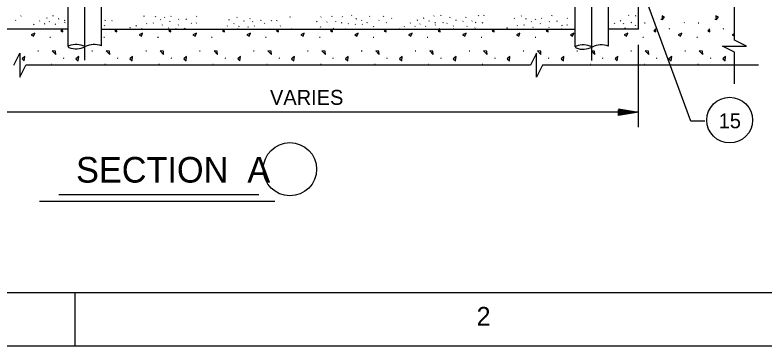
# Model space of a CAD drawing. Extents: x -0.2 to 13.5, y -0.2 to 9.5.
# Drawn here: x 7.896 to 10.235, y 0 to 1.035 of the extents above; entities that cross this region are included whole.
import ezdxf

# ---------------------------------------------------------------- set-up
doc = ezdxf.new("R2010")
doc.units = 0
for name, color, linetype in [('Level 0', 7, 'Continuous'), ('Level 1', 7, 'Continuous'), ('Level 13', 7, 'Continuous'), ('Level 2', 7, 'Continuous'), ('Level 3', 7, 'Continuous'), ('Level 50', 7, 'Continuous')]:
    doc.layers.add(name, color=color, linetype=linetype)

msp = doc.modelspace()

# ---------------------------------------------------------------- linework, layer by layer
at = {"layer": 'Level 0'}
for p, q in [((7.9157, 1.0321), (7.9145, 1.0308)), ((8.0152, 1.0323), (8.0134, 1.031)), ((8.2993, 1.0318), (8.2981, 1.0303)), ((8.3348, 1.03), (8.3336, 1.0286)), ((8.384, 1.0318), (8.3829, 1.0303)), ((8.4645, 1.0317), (8.4633, 1.0303)), ((8.7552, 1.0293), (8.7546, 1.0272)), ((8.8525, 1.0296), (8.8513, 1.0282)), ((8.8857, 1.0309), (8.8846, 1.0295)), ((8.9191, 1.0305), (8.9178, 1.0291)), ((8.9485, 1.0348), (8.9473, 1.0334)), ((9.0047, 1.0314), (9.0035, 1.03)), ((9.0475, 1.031), (9.0463, 1.0295)), ((9.2052, 1.0325), (9.204, 1.0311)), ((9.2259, 1.0342), (9.2247, 1.0328)), ((9.344, 1.0329), (9.3428, 1.0315)), ((9.36, 1.0342), (9.3588, 1.0328)), ((9.4778, 1.0323), (9.4766, 1.0309)), ((9.573, 1.0332), (9.5718, 1.0318)), ((9.8132, 1.0343), (9.812, 1.0329)), ((9.8348, 1.0321), (9.833, 1.0315)), ((7.8988, 1.0188), (7.8976, 1.0173)), ((7.9557, 1.006), (7.9545, 1.0046)), ((7.9739, 1.0172), (7.9727, 1.0158)), ((7.989, 1.0073), (7.9878, 1.0059)), ((7.9955, 1.0259), (7.9943, 1.0244)), ((8.0041, 1.0146), (8.0029, 1.0132)), ((8.0223, 1.0068), (8.0211, 1.0054)), ((8.0327, 1.0233), (8.0315, 1.0219)), ((8.052, 1.0174), (8.0499, 1.0169)), ((8.0517, 1.0112), (8.0505, 1.0098)), ((8.1775, 1.0185), (8.1764, 1.0171)), ((8.1997, 1.0178), (8.1982, 1.0163)), ((8.3084, 1.0088), (8.3072, 1.0074)), ((8.3292, 1.0106), (8.3279, 1.0092)), ((8.3521, 1.0214), (8.3509, 1.0199)), ((8.3642, 1.0283), (8.363, 1.0269)), ((8.3797, 1.0153), (8.3786, 1.0139)), ((8.4078, 1.0218), (8.4066, 1.0204)), ((8.4318, 1.0227), (8.4302, 1.0211)), ((8.4472, 1.0092), (8.446, 1.0079)), ((8.4632, 1.0106), (8.462, 1.0092)), ((8.5646, 1.0199), (8.5635, 1.0185)), ((8.5811, 1.0086), (8.5799, 1.0072)), ((8.5902, 1.0281), (8.589, 1.0267)), ((8.6112, 1.0163), (8.6101, 1.0143)), ((8.6304, 1.0242), (8.6292, 1.0228)), ((8.639, 1.0147), (8.6378, 1.0133)), ((8.6637, 1.0186), (8.6625, 1.0171)), ((8.6762, 1.0095), (8.675, 1.0081)), ((8.697, 1.0173), (8.6958, 1.0159)), ((8.7143, 1.0173), (8.7131, 1.0159)), ((8.8396, 1.0155), (8.838, 1.0139)), ((8.8711, 1.0137), (8.8699, 1.0123)), ((8.8976, 1.0149), (8.8969, 1.0133)), ((8.9165, 1.0106), (8.9153, 1.0092)), ((8.938, 1.0084), (8.9362, 1.0078)), ((8.9601, 1.0067), (8.9589, 1.0053)), ((8.9623, 1.0236), (8.9611, 1.0222)), ((8.9796, 1.0193), (8.9784, 1.0178)), ((8.9813, 1.0059), (8.98, 1.0049)), ((8.9965, 1.0111), (8.9953, 1.0097)), ((9.0337, 1.0188), (9.0325, 1.0174)), ((9.0561, 1.0119), (9.055, 1.0105)), ((9.0731, 1.0253), (9.0719, 1.0239)), ((9.1312, 1.0104), (9.13, 1.009)), ((9.1528, 1.0191), (9.1516, 1.0176)), ((9.1615, 1.0078), (9.1603, 1.0064)), ((9.1725, 1.0255), (9.1707, 1.0242)), ((9.19, 1.0165), (9.1888, 1.015)), ((9.2094, 1.0106), (9.2072, 1.0101)), ((9.2333, 1.0113), (9.2321, 1.0099)), ((9.2462, 1.0096), (9.2451, 1.0082)), ((9.2541, 1.0277), (9.2528, 1.0263)), ((9.2735, 1.0186), (9.2723, 1.0173)), ((9.2959, 1.0156), (9.2945, 1.0146)), ((9.3042, 1.0278), (9.303, 1.0263)), ((9.3236, 1.0169), (9.3225, 1.0155)), ((9.3349, 1.0117), (9.3337, 1.0103)), ((9.357, 1.011), (9.3556, 1.0095)), ((9.4566, 1.0249), (9.4555, 1.0235)), ((9.4921, 1.0232), (9.4909, 1.0218)), ((9.5094, 1.0145), (9.5082, 1.0131)), ((9.5215, 1.0215), (9.5203, 1.0201)), ((9.5371, 1.0085), (9.5359, 1.0071)), ((9.5414, 1.0249), (9.5402, 1.0235)), ((9.5652, 1.015), (9.564, 1.0136)), ((9.5891, 1.0159), (9.5875, 1.0143)), ((9.6218, 1.0249), (9.6206, 1.0235)), ((9.7685, 1.0095), (9.7674, 1.0075)), ((9.7877, 1.0174), (9.7865, 1.016)), ((9.7963, 1.0079), (9.7952, 1.0064)), ((9.821, 1.0118), (9.8198, 1.0103)), ((9.8638, 1.0094), (9.8616, 1.0094)), ((9.9151, 1.0206), (9.9134, 1.0207)), ((9.9873, 1.0108), (9.9856, 1.0111)), ((10.0321, 1.0094), (10.0299, 1.0094)), ((10.0834, 1.0206), (10.0818, 1.0207)), ((7.9429, 0.9918), (7.942, 0.9909)), ((8.0008, 0.9912), (8.0007, 0.9909)), ((8.1763, 1.0017), (8.1751, 1.0003)), ((8.2562, 0.9909), (8.2548, 0.9902)), ((8.2561, 0.9954), (8.2549, 0.994)), ((8.2757, 1.0018), (8.274, 1.0005)), ((8.2932, 0.9928), (8.2921, 0.9914)), ((8.3573, 1.0041), (8.3561, 1.0027)), ((8.3767, 0.995), (8.3755, 0.9936)), ((8.3991, 0.992), (8.3977, 0.991)), ((8.4074, 1.0041), (8.4062, 1.0027)), ((8.4245, 0.9909), (8.4231, 0.9902)), ((8.4269, 0.9933), (8.4257, 0.9919)), ((8.5599, 1.0013), (8.5587, 0.9999)), ((8.5929, 0.9909), (8.5915, 0.9902)), ((8.5953, 0.9996), (8.5941, 0.9981)), ((8.6247, 0.9978), (8.6235, 0.9964)), ((8.6446, 1.0013), (8.6434, 0.9999)), ((8.6684, 0.9913), (8.668, 0.9909)), ((8.6923, 0.9922), (8.691, 0.9909)), ((8.7251, 1.0013), (8.7239, 0.9999)), ((8.7612, 0.9909), (8.7598, 0.9902)), ((8.8507, 0.9976), (8.8495, 0.9963)), ((8.8909, 0.9938), (8.8898, 0.9924)), ((8.9295, 0.9909), (8.9281, 0.9902)), ((9.0158, 0.9988), (9.0151, 0.9968)), ((9.0979, 0.9909), (9.0965, 0.9902)), ((9.1131, 0.9992), (9.1118, 0.9978)), ((9.1463, 1.0005), (9.1451, 0.9991)), ((9.1796, 1), (9.1784, 0.9986)), ((9.209, 1.0044), (9.2079, 1.003)), ((9.2229, 0.9931), (9.2217, 0.9917)), ((9.2653, 1.0009), (9.2641, 0.9996)), ((9.2662, 0.9909), (9.2648, 0.9902)), ((9.3081, 1.0005), (9.3069, 0.9991)), ((9.3336, 0.9949), (9.3324, 0.9935)), ((9.4331, 0.995), (9.4313, 0.9937)), ((9.4345, 0.9909), (9.4331, 0.9902)), ((9.4657, 1.002), (9.4645, 1.0006)), ((9.4865, 1.0038), (9.4852, 1.0023)), ((9.5146, 0.9973), (9.5134, 0.9959)), ((9.5647, 0.9973), (9.5636, 0.9959)), ((9.6029, 0.9909), (9.6015, 0.9902)), ((9.6045, 1.0024), (9.6033, 1.0011)), ((9.6205, 1.0038), (9.6194, 1.0023)), ((9.7712, 0.9909), (9.7698, 0.9902)), ((9.7821, 0.991), (9.7819, 0.9909)), ((9.8019, 0.9945), (9.8008, 0.9931)), ((9.8336, 1.0027), (9.8324, 1.0013)), ((9.9401, 0.9912), (9.9381, 0.9902)), ((10.1085, 0.9912), (10.1065, 0.9902)), ((8.0073, 0.9643), (8.0052, 0.9643)), ((8.1756, 0.9643), (8.1735, 0.9643)), ((8.344, 0.9643), (8.3418, 0.9643)), ((8.5123, 0.9643), (8.5102, 0.9643)), ((8.6806, 0.9643), (8.6785, 0.9643)), ((8.849, 0.9643), (8.8468, 0.9643)), ((9.0173, 0.9643), (9.0152, 0.9643)), ((9.1856, 0.9643), (9.1835, 0.9643)), ((9.354, 0.9643), (9.3518, 0.9643)), ((9.5223, 0.9643), (9.5202, 0.9643)), ((9.859, 0.9643), (9.8568, 0.9643)), ((10.0273, 0.9643), (10.0252, 0.9643)), ((7.97, 0.9219), (7.9677, 0.9219)), ((8.1383, 0.9219), (8.1361, 0.9219)), ((8.3066, 0.9219), (8.3044, 0.9219)), ((8.475, 0.9219), (8.4727, 0.9219)), ((8.6433, 0.9219), (8.6411, 0.9219)), ((8.8116, 0.9219), (8.8094, 0.9219)), ((8.98, 0.9219), (8.9777, 0.9219)), ((9.1483, 0.9219), (9.1461, 0.9219)), ((9.3166, 0.9219), (9.3144, 0.9219)), ((9.485, 0.9219), (9.4827, 0.9219)), ((9.6533, 0.9219), (9.6511, 0.9219)), ((9.8216, 0.9219), (9.8194, 0.9219)), ((9.99, 0.9219), (9.9877, 0.9219)), ((8.0497, 0.8994), (8.0476, 0.8997)), ((8.2181, 0.8994), (8.2159, 0.8997)), ((8.3864, 0.8994), (8.3842, 0.8997)), ((8.5547, 0.8994), (8.5526, 0.8997)), ((8.7231, 0.8994), (8.7209, 0.8997)), ((8.8914, 0.8994), (8.8892, 0.8997)), ((9.0597, 0.8994), (9.0576, 0.8997)), ((9.2281, 0.8994), (9.2259, 0.8997)), ((9.3964, 0.8994), (9.3942, 0.8997)), ((9.5647, 0.8994), (9.5626, 0.8997)), ((9.7331, 0.8994), (9.7309, 0.8997)), ((9.9014, 0.8994), (9.8992, 0.8997)), ((10.0697, 0.8994), (10.0676, 0.8997)), ((7.9718, 0.8782), (7.9706, 0.8779)), ((8.0106, 0.8805), (8.009, 0.8799)), ((8.1401, 0.8782), (8.139, 0.8779)), ((8.1789, 0.8805), (8.1773, 0.8799)), ((8.3084, 0.8782), (8.3073, 0.8779)), ((8.3473, 0.8805), (8.3456, 0.8799)), ((8.4768, 0.8782), (8.4756, 0.8779)), ((8.5156, 0.8805), (8.514, 0.8799)), ((8.6451, 0.8782), (8.644, 0.8779)), ((8.6839, 0.8805), (8.6823, 0.8799)), ((8.8134, 0.8782), (8.8123, 0.8779)), ((8.8523, 0.8805), (8.8506, 0.8799)), ((8.9818, 0.8782), (8.9806, 0.8779)), ((9.0206, 0.8805), (9.019, 0.8799)), ((9.1501, 0.8782), (9.149, 0.8779)), ((9.1889, 0.8805), (9.1873, 0.8799)), ((9.3184, 0.8782), (9.3173, 0.8779)), ((9.3573, 0.8805), (9.3556, 0.8799)), ((9.4868, 0.8782), (9.4856, 0.8779)), ((9.5256, 0.8805), (9.524, 0.8799)), ((9.6551, 0.8782), (9.654, 0.8779)), ((9.6939, 0.8805), (9.6923, 0.8799)), ((9.8234, 0.8782), (9.8223, 0.8779)), ((9.8623, 0.8805), (9.8606, 0.8799)), ((9.9918, 0.8782), (9.9906, 0.8779)), ((10.0306, 0.8805), (10.029, 0.8799))]:
    msp.add_line(p, q, dxfattribs=at)
for points in [[(9.9175, 1.02), (9.9246, 1.028), (9.9167, 1.0322)], [(10.0858, 1.02), (10.093, 1.028), (10.085, 1.0322)], [(9.8975, 0.9827), (9.8963, 0.9919), (9.8912, 0.9842)], [(10.0658, 0.9827), (10.0646, 0.9919), (10.0595, 0.9842)], [(7.9542, 0.9684), (7.9582, 0.9786), (7.9471, 0.9732)], [(8.2909, 0.9684), (8.2948, 0.9786), (8.2838, 0.9732)], [(8.4592, 0.9684), (8.4632, 0.9786), (8.4521, 0.9732)], [(8.6276, 0.9684), (8.6315, 0.9786), (8.6205, 0.9732)], [(8.7959, 0.9684), (8.7998, 0.9786), (8.7888, 0.9732)], [(8.9642, 0.9684), (8.9682, 0.9786), (8.9571, 0.9732)], [(9.1326, 0.9684), (9.1365, 0.9786), (9.1255, 0.9732)], [(9.3009, 0.9684), (9.3048, 0.9786), (9.2938, 0.9732)], [(9.4692, 0.9684), (9.4732, 0.9786), (9.4621, 0.9732)], [(9.6376, 0.9684), (9.6415, 0.9786), (9.6305, 0.9732)], [(9.8059, 0.9684), (9.8098, 0.9786), (9.7988, 0.9732)], [(9.9742, 0.9684), (9.9782, 0.9786), (9.9671, 0.9732)], [(8.0229, 0.9221), (8.0129, 0.9227), (8.0238, 0.9116)], [(8.1913, 0.9221), (8.1813, 0.9227), (8.1921, 0.9116)], [(8.3596, 0.9221), (8.3496, 0.9227), (8.3604, 0.9116)], [(8.5279, 0.9221), (8.5179, 0.9227), (8.5288, 0.9116)], [(8.6963, 0.9221), (8.6863, 0.9227), (8.6971, 0.9116)], [(8.8646, 0.9221), (8.8546, 0.9227), (8.8654, 0.9116)], [(9.0329, 0.9221), (9.0229, 0.9227), (9.0338, 0.9116)], [(9.2013, 0.9221), (9.1913, 0.9227), (9.2021, 0.9116)], [(9.3696, 0.9221), (9.3596, 0.9227), (9.3704, 0.9116)], [(9.5379, 0.9221), (9.5279, 0.9227), (9.5388, 0.9116)], [(9.7063, 0.9221), (9.6963, 0.9227), (9.7071, 0.9116)], [(9.8746, 0.9221), (9.8646, 0.9227), (9.8754, 0.9116)], [(10.0429, 0.9221), (10.0329, 0.9227), (10.0438, 0.9116)], [(7.9269, 0.9054), (7.9183, 0.8979), (7.9254, 0.8919)], [(8.0952, 0.9054), (8.0867, 0.8979), (8.0938, 0.8919)], [(8.2636, 0.9054), (8.255, 0.8979), (8.2621, 0.8919)], [(8.4319, 0.9054), (8.4233, 0.8979), (8.4304, 0.8919)], [(8.6002, 0.9054), (8.5917, 0.8979), (8.5988, 0.8919)], [(8.7686, 0.9054), (8.76, 0.8979), (8.7671, 0.8919)], [(8.9369, 0.9054), (8.9283, 0.8979), (8.9354, 0.8919)], [(9.1052, 0.9054), (9.0967, 0.8979), (9.1038, 0.8919)], [(9.2736, 0.9054), (9.265, 0.8979), (9.2721, 0.8919)], [(9.4419, 0.9054), (9.4333, 0.8979), (9.4404, 0.8919)], [(9.6102, 0.9054), (9.6017, 0.8979), (9.6088, 0.8919)], [(9.7786, 0.9054), (9.77, 0.8979), (9.7771, 0.8919)], [(9.9469, 0.9054), (9.9383, 0.8979), (9.9454, 0.8919)], [(10.1152, 0.9054), (10.1067, 0.8979), (10.1138, 0.8919)]]:
    msp.add_lwpolyline(points, close=True, dxfattribs=at)
for points in [[(8.044, 0.9909), (8.0395, 0.9842), (8.0458, 0.9827)], [(8.0458, 0.9827), (8.0448, 0.9909)], [(8.2123, 0.9909), (8.2078, 0.9842), (8.2141, 0.9827)], [(8.2141, 0.9827), (8.2131, 0.9909)], [(8.3806, 0.9909), (8.3762, 0.9842), (8.3825, 0.9827)], [(8.3825, 0.9827), (8.3814, 0.9909)], [(8.549, 0.9909), (8.5445, 0.9842), (8.5508, 0.9827)], [(8.5508, 0.9827), (8.5498, 0.9909)], [(8.7173, 0.9909), (8.7128, 0.9842), (8.7191, 0.9827)], [(8.7191, 0.9827), (8.7181, 0.9909)], [(8.8856, 0.9909), (8.8812, 0.9842), (8.8875, 0.9827)], [(8.8875, 0.9827), (8.8864, 0.9909)], [(9.054, 0.9909), (9.0495, 0.9842), (9.0558, 0.9827)], [(9.0558, 0.9827), (9.0548, 0.9909)], [(9.2223, 0.9909), (9.2178, 0.9842), (9.2241, 0.9827)], [(9.2241, 0.9827), (9.2231, 0.9909)], [(9.3906, 0.9909), (9.3862, 0.9842), (9.3925, 0.9827)], [(9.3925, 0.9827), (9.3914, 0.9909)], [(9.559, 0.9909), (9.5545, 0.9842), (9.5608, 0.9827)], [(9.5608, 0.9827), (9.5598, 0.9909)], [(10.1435, 0.9772), (10.1355, 0.9732), (10.1426, 0.9684)], [(10.1426, 0.9684), (10.1435, 0.971)]]:
    msp.add_lwpolyline(points, dxfattribs=at)
at = {"layer": 'Level 1'}
msp.add_line((8.0833, 0.1667), (8.0833, 0), dxfattribs=at)
for points in [[(0, 9.3333), (13.3333, 9.3333), (13.3333, 0), (0, 0)], [(0.5, 9.1667), (13.1667, 9.1667), (13.1667, 0.1667), (0.5, 0.1667)]]:
    msp.add_lwpolyline(points, close=True, dxfattribs=at)
at = {"layer": 'Level 13'}
for p, q in [((8.0619, 0.9365), (8.0619, 1.1144)), ((8.1661, 0.9389), (8.1661, 1.1144)), ((9.6452, 0.9354), (9.6452, 1.1132)), ((9.7494, 0.9377), (9.7494, 1.1132))]:
    msp.add_line(p, q, dxfattribs=at)
for points in [[(10.1435, 0.919), (10.106, 0.9376), (10.181, 0.9376), (10.1435, 0.9563)], [(7.8929, 0.8779), (7.9115, 0.9154), (7.9115, 0.8405), (7.9303, 0.8779)], [(9.543, 0.8779), (9.5244, 0.8404), (9.5244, 0.9153), (9.5057, 0.8779)]]:
    msp.add_lwpolyline(points, dxfattribs=at)
for centre, radius, start, end in [((8.0659, 0.9359), 0.00313, 110.1936, 249.8064), ((8.0869, 0.879), 0.0638, 63.3929, 110.1936), ((8.0869, 0.9929), 0.0638, 249.8064, 296.6071), ((8.144, 0.879), 0.0638, 69.8081, 116.6071), ((9.6493, 0.9348), 0.00313, 110.1936, 249.8064), ((9.6702, 0.8778), 0.0638, 63.3929, 110.1936), ((9.7274, 0.8778), 0.0638, 69.8081, 116.6071), ((9.6702, 0.9917), 0.0638, 249.8064, 296.6071)]:
    msp.add_arc(centre, radius, start, end, dxfattribs=at)
at = {"layer": 'Level 2'}
for p, q in [((8.114, 0.8941), (8.114, 1.4695)), ((9.6973, 0.893), (9.6973, 1.4684)), ((9.8431, 0.9909), (9.8431, 1.3242)), ((10.1435, 0.9563), (10.1435, 1.2171)), ((8.0619, 0.9909), (7.8119, 0.9909)), ((8.1661, 0.9909), (9.6452, 0.9909)), ((9.8431, 0.9909), (9.7494, 0.9909)), ((9.8431, 0.6846), (9.8431, 0.9419)), ((10.1435, 0.82), (10.1435, 0.919)), ((9.5057, 0.8779), (7.9303, 0.8779)), ((10.218, 0.8779), (9.543, 0.8779)), ((9.8431, 0.7308), (7.8119, 0.7308))]:
    msp.add_line(p, q, dxfattribs=at)
msp.add_circle((10.1281, 0.7063), 0.0714, dxfattribs=at)
at = {"layer": 'Level 3'}
for p, q in [((8.0335, 0.4739), (8.6582, 0.4739)), ((7.9731, 0.453), (8.7079, 0.453))]:
    msp.add_line(p, q, dxfattribs=at)
msp.add_lwpolyline([(10.0506, 0.7033), (10.0068, 0.7033), (9.8061, 1.2507)], dxfattribs=at)
msp.add_circle((8.7549, 0.5528), 0.0833, dxfattribs=at)
at = {"layer": 'Level 50'}
for p, q in [((9.8258, 0.7308), (9.8258, 0.7308)), ((9.8431, 0.7308), (9.8431, 0.7308))]:
    msp.add_line(p, q, dxfattribs=at)
msp.add_lwpolyline([(9.7808, 0.7412), (9.8431, 0.7308), (9.7808, 0.7205), (9.7808, 0.7382), (9.8258, 0.7308), (9.7835, 0.7238), (9.7835, 0.7352), (9.8091, 0.7308), (9.7861, 0.7272), (9.7861, 0.7318), (9.7918, 0.7308)], dxfattribs=at)

# ---------------------------------------------------------------- texts
at = {"layer": 'Level 1'}
msp.add_text('2', height=0.0584, dxfattribs=at).set_placement((9.3378, 0.0638))
at = {"layer": 'Level 2'}
for s, p in [('VARIES', (8.6926, 0.7541)), ('15', (10.0937, 0.6808))]:
    msp.add_text(s, height=0.0467, dxfattribs=at).set_placement(p)
at = {"layer": 'Level 3'}
msp.add_text('SECTION  A', height=0.08, dxfattribs=at).set_placement((8.087, 0.511))

doc.saveas('drawing.dxf')
